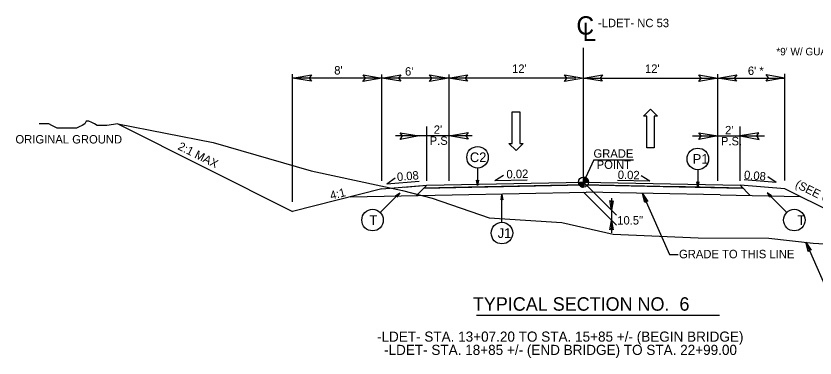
# Model space of a CAD drawing. Extents: x 1548135 to 1549339, y 868664 to 869085.
# Drawn here: x 1548314.3 to 1548385.7, y 868731.2 to 868761.8 of the extents above; entities that cross this region are included whole.
import ezdxf

# ---------------------------------------------------------------- set-up
doc = ezdxf.new("R2010")
doc.units = 0
for name, color, linetype in [('P_RDY_TC_Pvmt_Asphalt_Base_Course', 7, 'Continuous'), ('Prop Dimension', 7, 'Continuous'), ('Prop Dimension Text', 7, 'Continuous'), ('Prop Terminator CELL', 7, 'Continuous'), ('Sheet_Data_Field_CELL', 7, 'Continuous'), ('Sheet_Plan', 7, 'Continuous'), ('Sheet_Title_Block_Text', 7, 'Continuous'), ('Typical Curb CELL', 7, 'Continuous'), ('Typical Grade Point Symbol CELL', 7, 'Continuous'), ('Typical Hinge Slope Arterial CELL', 7, 'Continuous'), ('Typical Hinge Slope Interstate CELL', 7, 'Continuous'), ('Typical Pavement Slope CELL', 7, 'Continuous'), ('Typical Pavement Slope Information CELL', 7, 'Continuous'), ('Typical Shoulder Slope CELL', 7, 'Continuous'), ('Typical Shoulder Slope Information CELL', 7, 'Continuous'), ('Typical Terminator CELL', 7, 'Continuous'), ('Typical Text Centerline CELL', 7, 'Continuous'), ('Typical Text General CELL', 7, 'Continuous'), ('Typical Text Grade Point CELL', 7, 'Continuous'), ('z - Construction', 7, 'Continuous')]:
    doc.layers.add(name, color=color, linetype=linetype)

msp = doc.modelspace()

# ---------------------------------------------------------------- linework, layer by layer
at = {"layer": 'P_RDY_TC_Pvmt_Asphalt_Base_Course'}
for points in [[(1548340.739, 868755.947), (1548339.052, 868756.238), (1548340.749, 868756.538), (1548340.533, 868756.238)], [(1548345.362, 868756.528), (1548347.05, 868756.238), (1548345.353, 868755.938), (1548345.569, 868756.238)], [(1548348.737, 868755.947), (1548347.05, 868756.238), (1548348.747, 868756.538), (1548348.531, 868756.238)], [(1548351.303, 868756.528), (1548352.99, 868756.238), (1548351.294, 868755.938), (1548351.509, 868756.238)], [(1548354.678, 868755.947), (1548352.99, 868756.238), (1548354.687, 868756.538), (1548354.472, 868756.238)], [(1548363.362, 868756.528), (1548365.05, 868756.238), (1548363.353, 868755.938), (1548363.569, 868756.238)], [(1548366.737, 868755.947), (1548365.05, 868756.238), (1548366.747, 868756.538), (1548366.531, 868756.238)], [(1548375.362, 868756.528), (1548377.05, 868756.238), (1548375.353, 868755.938), (1548375.569, 868756.238)], [(1548378.737, 868755.947), (1548377.05, 868756.238), (1548378.747, 868756.538), (1548378.531, 868756.238)], [(1548381.374, 868756.546), (1548383.061, 868756.256), (1548381.364, 868755.956), (1548381.58, 868756.256)], [(1548348.675, 868751.355), (1548350.362, 868751.065), (1548348.665, 868750.765), (1548348.881, 868751.065)], [(1548354.737, 868750.774), (1548353.05, 868751.065), (1548354.747, 868751.365), (1548354.531, 868751.065)], [(1548375.362, 868751.355), (1548377.05, 868751.065), (1548375.353, 868750.765), (1548375.569, 868751.065)], [(1548380.737, 868751.355), (1548379.05, 868751.065), (1548380.747, 868750.765), (1548380.531, 868751.065)]]:
    msp.add_lwpolyline(points, close=True, dxfattribs=at)
at = {"layer": 'Prop Dimension'}
msp.add_line((1548393.699, 868741.018), (1548383.061, 868746.337), dxfattribs=at)
at = {"layer": 'Prop Dimension Text'}
for p, q in [((1548350.799, 868746.416), (1548365.05, 868746.701)), ((1548365.05, 868746.701), (1548379.3, 868746.416))]:
    msp.add_line(p, q, dxfattribs=at)
at = {"layer": 'Prop Terminator CELL'}
msp.add_lwpolyline([(1548351.05, 868746.671), (1548365.05, 868746.951), (1548379.05, 868746.671), (1548379.3, 868746.416), (1548375.475, 868746.493), (1548374.175, 868746.519), (1548371.891, 868746.564), (1548365.05, 868746.701), (1548365.05, 868746.701), (1548354.786, 868746.496), (1548350.799, 868746.416)], close=True, dxfattribs=at)
at = {"layer": 'Sheet_Data_Field_CELL'}
for p in [(1548323.451, 868752.137), (1548347.05, 868746.338)]:
    msp.add_line(p, (1548339.05, 868744.338), dxfattribs=at)
msp.add_lwpolyline([(1548323.451, 868752.137), (1548322.466, 868752.015), (1548322.22, 868752.015), (1548321.849, 868752.015), (1548321.603, 868752.015), (1548321.357, 868752.137), (1548321.11, 868752.261), (1548320.864, 868752.385), (1548320.618, 868752.385), (1548320.494, 868752.137), (1548320.248, 868752.015), (1548320.001, 868751.891), (1548319.755, 868751.768), (1548319.508, 868751.768), (1548319.262, 868751.768), (1548319.016, 868751.768), (1548318.769, 868751.768), (1548318.523, 868751.768), (1548318.277, 868751.768), (1548318.03, 868751.768), (1548317.784, 868751.891), (1548317.538, 868752.015), (1548317.291, 868752.137), (1548316.921, 868752.137), (1548316.675, 868752.137), (1548316.428, 868752.137)], dxfattribs=at)
at = {"layer": 'Sheet_Plan'}
for p, q in [((1548347.05, 868746.338), (1548351.05, 868746.671)), ((1548383.061, 868746.337), (1548379.05, 868746.671))]:
    msp.add_line(p, q, dxfattribs=at)
at = {"layer": 'Typical Curb CELL'}
for p, q in [((1548364.602, 868746.951), (1548365.05, 868746.951)), ((1548365.049, 868746.504), (1548365.05, 868746.951)), ((1548365.05, 868746.951), (1548365.049, 868746.504)), ((1548365.05, 868746.951), (1548365.05, 868747.399)), ((1548365.497, 868746.951), (1548365.05, 868746.951))]:
    msp.add_line(p, q, dxfattribs=at)
for points in [[(1548364.604, 868746.951), (1548364.604, 868746.903)], [(1548364.613, 868746.951), (1548364.613, 868746.85)], [(1548364.622, 868746.951), (1548364.622, 868746.818)], [(1548364.631, 868746.951), (1548364.631, 868746.791)], [(1548364.64, 868746.951), (1548364.64, 868746.77)], [(1548364.649, 868746.951), (1548364.649, 868746.751)], [(1548364.658, 868746.951), (1548364.658, 868746.735)], [(1548364.667, 868746.951), (1548364.667, 868746.719)], [(1548364.676, 868746.951), (1548364.676, 868746.705)], [(1548364.685, 868746.951), (1548364.685, 868746.692)], [(1548364.694, 868746.951), (1548364.694, 868746.68)], [(1548364.703, 868746.951), (1548364.703, 868746.669)], [(1548364.712, 868746.951), (1548364.712, 868746.658)], [(1548364.721, 868746.951), (1548364.721, 868746.648)], [(1548364.73, 868746.951), (1548364.73, 868746.638)], [(1548364.739, 868746.951), (1548364.739, 868746.629)], [(1548364.747, 868746.951), (1548364.747, 868746.621)], [(1548364.756, 868746.951), (1548364.756, 868746.613)], [(1548364.765, 868746.951), (1548364.765, 868746.605)], [(1548364.774, 868746.951), (1548364.774, 868746.598)], [(1548364.783, 868746.951), (1548364.783, 868746.591)], [(1548364.792, 868746.951), (1548364.792, 868746.585)], [(1548364.801, 868746.951), (1548364.801, 868746.579)], [(1548364.81, 868746.951), (1548364.81, 868746.573)], [(1548364.819, 868746.951), (1548364.819, 868746.567)], [(1548364.828, 868746.951), (1548364.828, 868746.562)], [(1548364.837, 868746.951), (1548364.837, 868746.557)], [(1548364.846, 868746.951), (1548364.846, 868746.552)], [(1548364.855, 868746.951), (1548364.855, 868746.549)], [(1548364.864, 868746.951), (1548364.864, 868746.545)], [(1548364.873, 868746.951), (1548364.873, 868746.541)], [(1548364.882, 868746.951), (1548364.882, 868746.537)], [(1548364.891, 868746.951), (1548364.891, 868746.533)], [(1548364.9, 868746.951), (1548364.9, 868746.53)], [(1548364.909, 868746.951), (1548364.909, 868746.527)], [(1548364.918, 868746.951), (1548364.918, 868746.524)], [(1548364.927, 868746.951), (1548364.927, 868746.522)], [(1548364.935, 868746.951), (1548364.935, 868746.519)], [(1548364.944, 868746.951), (1548364.944, 868746.517)], [(1548364.953, 868746.951), (1548364.953, 868746.515)], [(1548364.962, 868746.951), (1548364.962, 868746.513)], [(1548364.971, 868746.951), (1548364.971, 868746.511)], [(1548364.98, 868746.951), (1548364.98, 868746.51)], [(1548364.989, 868746.951), (1548364.989, 868746.508)], [(1548364.998, 868746.951), (1548364.998, 868746.507)], [(1548365.007, 868746.951), (1548365.007, 868746.506)], [(1548365.016, 868746.951), (1548365.016, 868746.505)], [(1548365.025, 868746.951), (1548365.025, 868746.505)], [(1548365.034, 868746.951), (1548365.034, 868746.504)], [(1548365.043, 868746.951), (1548365.043, 868746.504), (1548365.043, 868746.504)], [(1548365.054, 868747.399), (1548365.054, 868747.399), (1548365.054, 868746.951)], [(1548365.063, 868747.399), (1548365.063, 868746.951)], [(1548365.072, 868747.398), (1548365.072, 868746.951)], [(1548365.081, 868747.398), (1548365.081, 868746.951)], [(1548365.09, 868747.397), (1548365.09, 868746.951)], [(1548365.099, 868747.396), (1548365.099, 868746.951)], [(1548365.108, 868747.395), (1548365.108, 868746.951)], [(1548365.117, 868747.394), (1548365.117, 868746.951)], [(1548365.125, 868747.393), (1548365.125, 868746.951)], [(1548365.134, 868747.391), (1548365.134, 868746.951)], [(1548365.143, 868747.389), (1548365.143, 868746.951)], [(1548365.152, 868747.387), (1548365.152, 868746.951)], [(1548365.161, 868747.385), (1548365.161, 868746.951)], [(1548365.17, 868747.382), (1548365.17, 868746.951)], [(1548365.179, 868747.38), (1548365.179, 868746.951)], [(1548365.188, 868747.377), (1548365.188, 868746.951)], [(1548365.197, 868747.374), (1548365.197, 868746.951)], [(1548365.206, 868747.371), (1548365.206, 868746.951)], [(1548365.215, 868747.367), (1548365.215, 868746.951)], [(1548365.224, 868747.363), (1548365.224, 868746.951)], [(1548365.233, 868747.359), (1548365.233, 868746.951)], [(1548365.242, 868747.355), (1548365.242, 868746.951)], [(1548365.251, 868747.351), (1548365.251, 868746.951)], [(1548365.26, 868747.346), (1548365.26, 868746.951)], [(1548365.269, 868747.341), (1548365.269, 868746.951)], [(1548365.278, 868747.336), (1548365.278, 868746.951)], [(1548365.287, 868747.331), (1548365.287, 868746.951)], [(1548365.296, 868747.325), (1548365.296, 868746.951)], [(1548365.304, 868747.319), (1548365.304, 868746.951)], [(1548365.313, 868747.312), (1548365.313, 868746.951)], [(1548365.322, 868747.306), (1548365.322, 868746.951)], [(1548365.331, 868747.299), (1548365.331, 868746.951)], [(1548365.34, 868747.292), (1548365.34, 868746.951)], [(1548365.349, 868747.284), (1548365.349, 868746.951)], [(1548365.358, 868747.276), (1548365.358, 868746.951)], [(1548365.367, 868747.267), (1548365.367, 868746.951)], [(1548365.376, 868747.258), (1548365.376, 868746.951)], [(1548365.385, 868747.248), (1548365.385, 868746.951)], [(1548365.394, 868747.237), (1548365.394, 868746.951)], [(1548365.403, 868747.226), (1548365.403, 868746.951)], [(1548365.412, 868747.214), (1548365.412, 868746.951)], [(1548365.421, 868747.201), (1548365.421, 868746.951)], [(1548365.43, 868747.187), (1548365.43, 868746.951)], [(1548365.439, 868747.172), (1548365.439, 868746.951)], [(1548365.448, 868747.156), (1548365.448, 868746.951)], [(1548365.457, 868747.137), (1548365.457, 868746.951)], [(1548365.466, 868747.116), (1548365.466, 868746.951)], [(1548365.475, 868747.092), (1548365.475, 868746.951)], [(1548365.484, 868747.061), (1548365.484, 868746.951)], [(1548365.492, 868747.015), (1548365.492, 868746.951)]]:
    msp.add_lwpolyline(points, dxfattribs=at)
msp.add_circle((1548365.049, 868746.951), 0.448, dxfattribs=at)
for start, end in [(179.99048, 269.99048), (359.99048, 89.99048)]:
    msp.add_arc((1548365.049, 868746.951), 0.448, start, end, dxfattribs=at)
at = {"layer": 'Typical Grade Point Symbol CELL'}
for p, q in [((1548365.05, 868746.951), (1548365.05, 868758.944)), ((1548339.05, 868745.187), (1548339.05, 868756.583)), ((1548339.05, 868747.052), (1548339.05, 868756.563)), ((1548364.362, 868756.238), (1548339.05, 868756.238)), ((1548347.05, 868747.052), (1548347.05, 868756.563)), ((1548351.362, 868756.238), (1548349.362, 868756.238)), ((1548353.05, 868747.071), (1548353.05, 868756.563)), ((1548365.05, 868756.238), (1548383.061, 868756.238)), ((1548377.05, 868747.071), (1548377.05, 868756.583)), ((1548377.05, 868747.071), (1548377.05, 868756.583)), ((1548378.05, 868756.238), (1548380.05, 868756.238)), ((1548383.061, 868747.089), (1548383.061, 868756.601)), ((1548351.05, 868747.071), (1548351.05, 868751.915)), ((1548379.05, 868747.071), (1548379.05, 868751.915)), ((1548355.103, 868751.065), (1548348.255, 868751.065)), ((1548374.8, 868751.065), (1548381.23, 868751.065))]:
    msp.add_line(p, q, dxfattribs=at)
at = {"layer": 'Typical Hinge Slope Arterial CELL'}
msp.add_line((1548365.974, 868748.938), (1548369.531, 868748.938), dxfattribs=at)
at = {"layer": 'Typical Hinge Slope Interstate CELL'}
for p, q in [((1548355.59, 868748.205), (1548355.59, 868746.643)), ((1548375.271, 868748.059), (1548375.271, 868746.497)), ((1548368.001, 868744), (1548365.05, 868746.951)), ((1548349.05, 868746.505), (1548351.05, 868746.671)), ((1548351.05, 868746.671), (1548350.138, 868745.743)), ((1548346.887, 868744.239), (1548348.645, 868745.996)), ((1548353.332, 868745.807), (1548365.3, 868746.046)), ((1548357.767, 868743.358), (1548357.767, 868745.843)), ((1548368, 868743.09), (1548365.049, 868746.041)), ((1548377.27, 868745.807), (1548365.3, 868746.046)), ((1548367.555, 868745.525), (1548367.557, 868742.434)), ((1548383.213, 868744.239), (1548381.455, 868745.996))]:
    msp.add_line(p, q, dxfattribs=at)
for points in [[(1548323.451, 868752.137), (1548331.958, 868750.471), (1548340.725, 868747.96), (1548348.891, 868746.191), (1548351.527, 868745.504), (1548356.62, 868743.747), (1548363.126, 868743.34), (1548367.711, 868742.308), (1548375.305, 868741.975), (1548381.608, 868741.944), (1548385.593, 868741.508), (1548393.699, 868741.018)], [(1548370.328, 868745.946), (1548372.753, 868740.481), (1548373.504, 868740.481)], [(1548384.912, 868741.583), (1548387.336, 868736.118), (1548388.087, 868736.118)]]:
    msp.add_lwpolyline(points, dxfattribs=at)
for points in [[(1548355.671, 868747.111), (1548355.59, 868746.643), (1548355.507, 868747.114), (1548355.59, 868747.054)], [(1548375.351, 868746.966), (1548375.271, 868746.497), (1548375.187, 868746.968), (1548375.271, 868746.908)], [(1548348.256, 868745.722), (1548348.645, 868745.996), (1548348.37, 868745.604), (1548348.354, 868745.705)], [(1548357.686, 868745.375), (1548357.767, 868745.843), (1548357.85, 868745.372), (1548357.767, 868745.432)], [(1548370.538, 868745.115), (1548370.328, 868745.946), (1548370.81, 868745.231), (1548370.629, 868745.269)], [(1548381.844, 868745.722), (1548381.455, 868745.996), (1548381.729, 868745.604), (1548381.746, 868745.705)], [(1548367.7, 868745.29), (1548367.555, 868744.446), (1548367.405, 868745.295), (1548367.555, 868745.187)], [(1548367.409, 868742.691), (1548367.555, 868743.535), (1548367.705, 868742.687), (1548367.555, 868742.794)], [(1548385.121, 868740.753), (1548384.912, 868741.583), (1548385.393, 868740.868), (1548385.212, 868740.906)]]:
    msp.add_lwpolyline(points, close=True, dxfattribs=at)
for centre in [(1548355.59, 868749.166), (1548375.271, 868749.021), (1548346.207, 868743.558), (1548383.893, 868743.558), (1548357.767, 868742.396)]:
    msp.add_circle(centre, 0.962, dxfattribs=at)
at = {"layer": 'Typical Pavement Slope CELL'}
msp.add_line((1548351.05, 868746.671), (1548365.05, 868746.951), dxfattribs=at)
at = {"layer": 'Typical Pavement Slope Information CELL'}
for p, q in [((1548347.484, 868746.803), (1548348.235, 868747.325)), ((1548347.484, 868746.803), (1548350.367, 868747.043)), ((1548357.133, 868747.084), (1548357.916, 868747.557)), ((1548357.133, 868747.084), (1548360.025, 868747.142)), ((1548370.984, 868747.041), (1548368.092, 868747.099)), ((1548370.984, 868747.041), (1548370.201, 868747.514)), ((1548382.283, 868746.903), (1548379.4, 868747.143)), ((1548382.283, 868746.903), (1548381.531, 868747.425))]:
    msp.add_line(p, q, dxfattribs=at)
at = {"layer": 'Typical Shoulder Slope CELL'}
msp.add_line((1548365.974, 868748.938), (1548365.05, 868746.951), dxfattribs=at)
at = {"layer": 'Typical Shoulder Slope Information CELL'}
for p, q in [((1548370.414, 868752.821), (1548371.034, 868753.451)), ((1548371.034, 868753.451), (1548371.674, 868752.821)), ((1548358.696, 868750.407), (1548358.696, 868753.207)), ((1548358.696, 868753.207), (1548359.356, 868753.207)), ((1548359.356, 868753.207), (1548359.356, 868750.407)), ((1548370.714, 868752.821), (1548370.414, 868752.821)), ((1548370.714, 868750.021), (1548370.714, 868752.821)), ((1548371.674, 868752.821), (1548371.374, 868752.821)), ((1548371.374, 868752.821), (1548371.374, 868750.021)), ((1548359.036, 868749.777), (1548358.396, 868750.407)), ((1548358.396, 868750.407), (1548358.696, 868750.407)), ((1548359.656, 868750.407), (1548359.036, 868749.777)), ((1548359.356, 868750.407), (1548359.656, 868750.407)), ((1548371.374, 868750.021), (1548370.714, 868750.021))]:
    msp.add_line(p, q, dxfattribs=at)
at = {"layer": 'Typical Terminator CELL'}
msp.add_line((1548355.498, 868735.067), (1548377.219, 868735.067), dxfattribs=at)
at = {"layer": 'Typical Text Grade Point CELL'}
for p, q in [((1548365.05, 868746.951), (1548379.05, 868746.671)), ((1548379.05, 868746.671), (1548379.951, 868745.753)), ((1548344.193, 868745.624), (1548353.332, 868745.807)), ((1548377.27, 868745.807), (1548384.408, 868745.664))]:
    msp.add_line(p, q, dxfattribs=at)

# ---------------------------------------------------------------- texts
at = {"layer": 'Sheet_Data_Field_CELL'}
msp.add_text('ORIGINAL GROUND', height=0.75, dxfattribs=at).set_placement((1548314.297, 868750.396))
for s, rotation, p in [('2:1 MAX', 333.43495, (1548328.74, 868749.901)), ('(SEE CROSS SECTIONS)', 333.43403, (1548383.905, 868746.517)), ('4:1', 14.03624, (1548342.507, 868745.368))]:
    msp.add_text(s, height=0.75, rotation=rotation, dxfattribs=at).set_placement(p)
at = {"layer": 'Sheet_Title_Block_Text'}
msp.add_text('C', height=1.64, dxfattribs=at).set_placement((1548364.423, 868760.112))
msp.add_text('L', height=1.641, rotation=359.9469, dxfattribs=at).set_placement((1548364.968, 868759.552))
at = {"layer": 'Typical Hinge Slope Arterial CELL'}
msp.add_text('TYPICAL SECTION NO.  6', height=1.2, dxfattribs=at).set_placement((1548355.172, 868735.469))
at = {"layer": 'Typical Hinge Slope Interstate CELL'}
for s, height, p in [('-LDET- NC 53', 0.75, (1548366.35, 868760.779)), ('C2', 0.8608, (1548354.904, 868748.736)), ('P1', 0.8608, (1548374.814, 868748.59)), ('T', 0.861, (1548345.924, 868743.128)), ('10.5"', 0.75, (1548368.069, 868743.161)), ('T', 0.861, (1548384.176, 868743.128)), ('J1', 0.8608, (1548357.388, 868741.966)), ('GRADE TO THIS LINE', 0.75, (1548373.592, 868740.151))]:
    msp.add_text(s, height=height, dxfattribs=at).set_placement(p)
at = {"layer": 'Typical Pavement Slope Information CELL'}
for rotation, p in [(1.45507, (1548358.182, 868747.278)), (358.85436, (1548368.112, 868747.233))]:
    msp.add_text('0.02', height=0.75, rotation=rotation, dxfattribs=at).set_placement(p)
at = {"layer": 'Typical Shoulder Slope CELL'}
for s, p in [("8'", (1548342.78, 868756.554)), ("6'", (1548349.109, 868756.456)), ("12'", (1548358.673, 868756.699)), ("12'", (1548370.55, 868756.699)), ("6' *", (1548379.742, 868756.513)), ('GRADE', (1548365.948, 868749.127)), ('POINT', (1548366.233, 868748.133))]:
    msp.add_text(s, height=0.75, dxfattribs=at).set_placement(p)
at = {"layer": 'Typical Text Centerline CELL'}
for s, p in [("2'", (1548351.677, 868751.258)), ("2'", (1548377.705, 868751.214)), ('P.S.', (1548351.308, 868750.275)), ('P.S.', (1548377.336, 868750.231))]:
    msp.add_text(s, height=0.75, dxfattribs=at).set_placement(p)
at = {"layer": 'Typical Text General CELL'}
for s, height, p in [("*9' W/ GUARDRAIL", 0.66824, (1548382.286, 868758.267)), ('-LDET- STA. 13+07.20 TO STA. 15+85 +/- (BEGIN BRIDGE)', 0.90387, (1548346.603, 868732.704)), ('-LDET- STA. 18+85 +/- (END BRIDGE) TO STA. 22+99.00 ', 0.90387, (1548347.233, 868731.519))]:
    msp.add_text(s, height=height, dxfattribs=at).set_placement(p)
at = {"layer": 'z - Construction'}
for rotation, p in [(4.76147, (1548348.417, 868747.037)), (355.23853, (1548379.375, 868747.241))]:
    msp.add_text('0.08', height=0.75, rotation=rotation, dxfattribs=at).set_placement(p)

doc.saveas('drawing.dxf')
